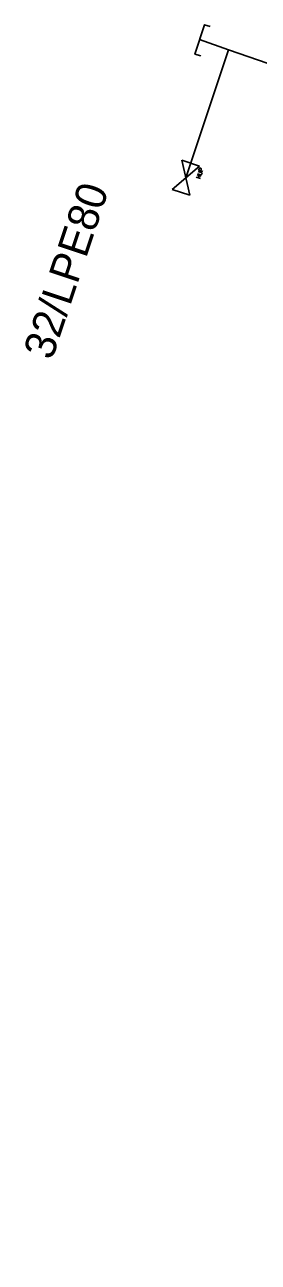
# Model space of a CAD drawing. Extents: x -741323 to -735641, y -1146295 to -1143223.
# Drawn here: x -736189.19 to -736181.59, y -1145442.23 to -1145401.99 of the extents above; entities that cross this region are included whole.
import ezdxf

# ---------------------------------------------------------------- set-up
doc = ezdxf.new("R2010")
doc.units = 0
for name, color, linetype in [('Vrstva 1', 7, 'Continuous'), ('Vrstva 21', 7, 'Continuous'), ('Vrstva 22', 7, 'Continuous'), ('Vrstva 31', 7, 'Continuous'), ('Vrstva 32', 7, 'Continuous')]:
    doc.layers.add(name, color=color, linetype=linetype)

# ---------------------------------------------------------------- blocks, each defined once
blk = doc.blocks.new('DEC063-SN')
at = {"layer": 'Vrstva 1'}
for p, q in [((-0.5, -0.3), (0.5, 0.3)), ((0.5, -0.3), (-0.5, 0.3)), ((-0.5, 0.3), (-0.5, -0.3)), ((0.5, 0.3), (0.5, -0.3)), ((0.126, -0.318), (0.126, -0.458)), ((0.126, -0.384), (0.206, -0.384)), ((0.206, -0.458), (0.206, -0.318)), ((0.366, -0.458), (0.366, -0.318))]:
    blk.add_line(p, q, dxfattribs=at)
for points in [[(0.246, -0.318), (0.246, -0.418), (0.252, -0.438), (0.264, -0.451), (0.281, -0.458), (0.292, -0.458), (0.309, -0.451), (0.321, -0.438), (0.326, -0.418), (0.326, -0.318)], [(0.366, -0.318), (0.418, -0.318), (0.435, -0.325), (0.441, -0.331), (0.446, -0.344), (0.446, -0.364), (0.441, -0.378), (0.435, -0.384), (0.418, -0.391), (0.366, -0.391)]]:
    blk.add_lwpolyline(points, dxfattribs=at)
blk = doc.blocks.new('DEC130')
at = {"layer": 'Vrstva 1'}
blk.add_lwpolyline([(0.2, 0.5), (0, 0.5), (0, -0.5), (0.2, -0.5)], dxfattribs=at)

msp = doc.modelspace()

# ---------------------------------------------------------------- linework, layer by layer
at = {"layer": 'Vrstva 21'}
msp.add_lwpolyline([(-736115.665, -1145439.308), (-736124.093, -1145435.685), (-736134.622, -1145442.227), (-736139.426, -1145437.026), (-736140.79, -1145435.55), (-736147.827, -1145427.981), (-736158.121, -1145418.624), (-736170.211, -1145407.42), (-736176.794, -1145404.793), (-736182.56, -1145402.808), (-736183.5, -1145402.47)], dxfattribs=at)
at = {"layer": 'Vrstva 31'}
msp.add_lwpolyline([(-736182.56, -1145402.808), (-736183.948, -1145406.97)], dxfattribs=at)

# ---------------------------------------------------------------- block references
at = {"layer": 'Vrstva 22', "rotation": -17.977597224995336}
msp.add_blockref('DEC130', (-736183.5, -1145402.47), dxfattribs=at)
at = {"layer": 'Vrstva 32', "rotation": 71.55679167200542}
msp.add_blockref('DEC063-SN', (-736183.948, -1145406.97), dxfattribs=at)

# ---------------------------------------------------------------- texts
at = {"layer": 'Vrstva 31'}
msp.add_text('32/LPE80', height=1, rotation=71.557, dxfattribs=at).set_placement((-736188.305, -1145412.926))

doc.saveas('drawing.dxf')
